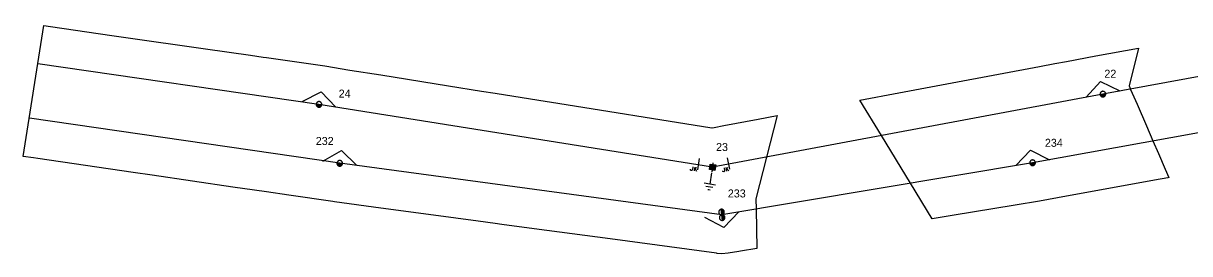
# Model space of a CAD drawing. Extents: x -540879 to -537255, y -1184046 to -1180016.
# Drawn here: x -539690.7 to -539435.6, y -1180909.4 to -1180859 of the extents above; entities that cross this region are included whole.
import ezdxf

# ---------------------------------------------------------------- set-up
doc = ezdxf.new("R2010")
doc.units = 0
for name, color, linetype in [('Vrstva 1', 7, 'Continuous'), ('Vrstva 13', 7, 'Continuous'), ('Vrstva 14', 7, 'Continuous'), ('Vrstva 15', 7, 'Continuous'), ('Vrstva 18', 7, 'Continuous'), ('Vrstva 2', 7, 'Continuous'), ('Vrstva 35', 7, 'Continuous')]:
    doc.layers.add(name, color=color, linetype=linetype)

# ---------------------------------------------------------------- blocks, each defined once
blk = doc.blocks.new('VN840')
at = {"layer": 'Vrstva 15'}
for points in [[(-0.01, 1.41), (-0.01, -1.09)], [(-1.51, -1.24), (-1.51, -1.15)], [(-1.48, -1.35), (-1.51, -1.24)], [(-1.33, -1.42), (-1.48, -1.35)], [(-1.27, -1.42), (-1.33, -1.42)], [(-1.13, -1.35), (-1.27, -1.42)], [(-1.09, -1.24), (-1.13, -1.35)], [(-1.09, -0.59), (-1.09, -1.24)], [(-0.68, -0.59), (-0.68, -1.42)], [(-0.68, -1.11), (-0.27, -0.59)], [(-0.54, -0.94), (-0.2, -1.42)]]:
    blk.add_lwpolyline(points, dxfattribs=at)
blk = doc.blocks.new('VN860')
at = {"layer": 'Vrstva 15'}
for points in [[(-3.74, 0), (0.01, 2.82)], [(0.01, 2.82), (3.76, 0)]]:
    blk.add_lwpolyline(points, dxfattribs=at)
blk = doc.blocks.new('VN440')
at = {"layer": 'Vrstva 2'}
for points in [[(1.22, 0), (1.21, 0.13), (1.19, 0.25), (1.16, 0.38), (1.11, 0.5), (1.05, 0.61), (0.98, 0.72), (0.9, 0.82), (0.81, 0.91), (0.71, 0.99), (0.6, 1.06), (0.49, 1.12), (0.37, 1.16), (0.25, 1.2), (0.12, 1.22), (-0.01, 1.22), (-0.14, 1.22), (-0.26, 1.2), (-0.39, 1.16), (-0.51, 1.12), (-0.62, 1.06), (-0.73, 0.99), (-0.83, 0.91), (-0.92, 0.82), (-1, 0.72), (-1.07, 0.61), (-1.13, 0.5), (-1.18, 0.38), (-1.21, 0.25), (-1.23, 0.13), (-1.24, 0), (-1.23, -0.13), (-1.21, -0.26), (-1.18, -0.38), (-1.13, -0.5), (-1.07, -0.62), (-1, -0.73), (-0.92, -0.83), (-0.83, -0.92), (-0.73, -1), (-0.62, -1.07), (-0.51, -1.13), (-0.39, -1.17), (-0.26, -1.2), (-0.14, -1.23), (-0.01, -1.23), (0.12, -1.23), (0.25, -1.2), (0.37, -1.17), (0.49, -1.13), (0.6, -1.07), (0.71, -1), (0.81, -0.92), (0.9, -0.83), (0.98, -0.73), (1.05, -0.62), (1.11, -0.5), (1.16, -0.38), (1.19, -0.26), (1.21, -0.13), (1.22, 0)], [(-1.24, 0), (1.22, 0)], [(-1.18, -0.34), (1.1, -0.34)], [(-1.01, -0.63), (0.97, -0.63)], [(-0.74, -0.92), (0.68, -0.92)]]:
    blk.add_lwpolyline(points, dxfattribs=at)
blk = doc.blocks.new('VN810')
at = {"layer": 'Vrstva 14'}
for points in [[(0, -1.25), (0, -3.75)], [(1.25, -3.75), (-1.25, -3.75)], [(0.77, -4.37), (-0.8, -4.37)], [(0, -5), (-0.25, -5)], [(0.27, -5), (0, -5)]]:
    blk.add_lwpolyline(points, dxfattribs=at)
blk = doc.blocks.new('VN450')
at = {"layer": 'Vrstva 2'}
for points in [[(0, 0), (-0.01, 0.13), (-0.03, 0.25), (-0.06, 0.38), (-0.11, 0.5), (-0.16, 0.61), (-0.23, 0.72), (-0.31, 0.82), (-0.4, 0.91), (-0.5, 0.99), (-0.61, 1.06), (-0.72, 1.11), (-0.84, 1.16), (-0.97, 1.19), (-1.09, 1.21), (-1.22, 1.22), (-1.35, 1.21), (-1.47, 1.19), (-1.59, 1.16), (-1.71, 1.11), (-1.83, 1.06), (-1.93, 0.99), (-2.03, 0.91), (-2.12, 0.82), (-2.2, 0.72), (-2.27, 0.61), (-2.33, 0.5), (-2.38, 0.38), (-2.41, 0.25), (-2.43, 0.13), (-2.44, 0), (-2.43, -0.13), (-2.41, -0.25), (-2.38, -0.38), (-2.33, -0.5), (-2.27, -0.61), (-2.2, -0.72), (-2.12, -0.82), (-2.03, -0.91), (-1.93, -0.99), (-1.83, -1.06), (-1.71, -1.11), (-1.59, -1.16), (-1.47, -1.19), (-1.35, -1.21), (-1.22, -1.22), (-1.09, -1.21), (-0.97, -1.19), (-0.84, -1.16), (-0.72, -1.11), (-0.61, -1.06), (-0.5, -0.99), (-0.4, -0.91), (-0.31, -0.82), (-0.23, -0.72), (-0.16, -0.61), (-0.11, -0.5), (-0.06, -0.38), (-0.03, -0.25), (-0.01, -0.13), (0, 0)], [(-2.44, 0), (2.44, 0)], [(2.44, 0), (2.43, 0.13), (2.41, 0.25), (2.38, 0.38), (2.33, 0.5), (2.27, 0.61), (2.2, 0.72), (2.12, 0.82), (2.03, 0.91), (1.94, 0.99), (1.83, 1.06), (1.71, 1.11), (1.6, 1.16), (1.47, 1.19), (1.35, 1.21), (1.22, 1.22), (1.09, 1.21), (0.97, 1.19), (0.84, 1.16), (0.72, 1.11), (0.61, 1.06), (0.5, 0.99), (0.4, 0.91), (0.31, 0.82), (0.23, 0.72), (0.16, 0.61), (0.11, 0.5), (0.06, 0.38), (0.03, 0.25), (0.01, 0.13), (0, 0), (0.01, -0.13), (0.03, -0.25), (0.06, -0.38), (0.11, -0.5), (0.16, -0.61), (0.23, -0.72), (0.31, -0.82), (0.4, -0.91), (0.5, -0.99), (0.61, -1.06), (0.72, -1.11), (0.84, -1.16), (0.97, -1.19), (1.09, -1.21), (1.22, -1.22), (1.35, -1.21), (1.47, -1.19), (1.6, -1.16), (1.71, -1.11), (1.83, -1.06), (1.94, -0.99), (2.03, -0.91), (2.12, -0.82), (2.2, -0.72), (2.27, -0.61), (2.33, -0.5), (2.38, -0.38), (2.41, -0.25), (2.43, -0.13), (2.44, 0)], [(-2.4, -0.31), (-0.04, -0.31)], [(-2.26, -0.61), (-0.17, -0.61)], [(-2.01, -0.92), (-0.42, -0.92)], [(0.04, -0.31), (2.4, -0.31)], [(0.17, -0.61), (2.27, -0.61)], [(0.42, -0.92), (2.02, -0.92)]]:
    blk.add_lwpolyline(points, dxfattribs=at)
blk = doc.blocks.new('VN470')
at = {"layer": 'Vrstva 2'}
for points in [[(-1.23, 1.22), (1.23, 1.22)], [(-1.23, -1.23), (-1.23, 1.22)], [(-0.92, 0.9), (0.92, 0.9)], [(-0.92, -0.95), (-0.92, 0.9)], [(-0.61, 0.61), (0.61, 0.61)], [(-0.61, -0.62), (-0.61, 0.61)], [(-0.31, -0.27), (-0.31, 0.34)], [(-0.31, 0.34), (0.31, 0.34)], [(0, 1.22), (0, 1.97)], [(0.31, 0.34), (0.31, -0.27)], [(0.61, 0.61), (0.61, -0.62)], [(0.92, 0.9), (0.92, -0.95)], [(1.23, 1.22), (1.23, -1.23)], [(1.23, -1.23), (-1.23, -1.23)], [(0.92, -0.95), (-0.92, -0.95)], [(0.61, -0.62), (-0.61, -0.62)], [(0.31, -0.27), (-0.31, -0.27)], [(0, -1.23), (0, -1.98)]]:
    blk.add_lwpolyline(points, dxfattribs=at)

msp = doc.modelspace()

# ---------------------------------------------------------------- linework, layer by layer
at = {"layer": 'Vrstva 1'}
for points in [[(-539368.99, -1180859.02), (-539384.94, -1180861.76), (-539454.57, -1180874.5), (-539539.93, -1180890.5), (-539626, -1180876.75), (-539687.49, -1180867.91)], [(-539376.35, -1180872.85), (-539386.09, -1180874.33), (-539469.94, -1180889.51), (-539537.91, -1180900.89), (-539621.46, -1180889.63), (-539689.34, -1180879.74)]]:
    msp.add_lwpolyline(points, dxfattribs=at)
at = {"layer": 'Vrstva 35'}
for points in [[(-539686.17, -1180859.51), (-539684.72, -1180859.72), (-539671.29, -1180861.65), (-539668.73, -1180862.02), (-539650.83, -1180864.59), (-539641, -1180866.01), (-539638.18, -1180866.41), (-539637.5, -1180866.51), (-539624.72, -1180868.35), (-539619.23, -1180869.23), (-539612.5, -1180870.3), (-539597.67, -1180872.67), (-539590.43, -1180873.82), (-539587.5, -1180874.29), (-539576.11, -1180876.11), (-539575.56, -1180876.2), (-539540.09, -1180881.88), (-539540.05, -1180881.87), (-539539.55, -1180881.78), (-539537.5, -1180881.39), (-539529.98, -1180879.98), (-539525.84, -1180879.21), (-539528.16, -1180888.29), (-539530.48, -1180897.39), (-539530.43, -1180899.63), (-539530.26, -1180908.22), (-539533.82, -1180908.82), (-539534.2, -1180908.88), (-539536.5, -1180909.27), (-539536.55, -1180909.27), (-539537.91, -1180909.39), (-539538.92, -1180909.32), (-539539.04, -1180909.3), (-539562.36, -1180906.17), (-539578.94, -1180903.93), (-539586.02, -1180902.98), (-539587.5, -1180902.78), (-539591.16, -1180902.29), (-539600.97, -1180900.97), (-539612.5, -1180899.41), (-539622.64, -1180898.05), (-539623, -1180898), (-539632.59, -1180896.6), (-539637.5, -1180895.88), (-539640.1, -1180895.5), (-539644.82, -1180894.82), (-539662.5, -1180892.24), (-539666.64, -1180891.64), (-539687.5, -1180888.6), (-539688.46, -1180888.46), (-539690.66, -1180888.14)], [(-539448.84, -1180872.69), (-539448.54, -1180873.4), (-539448.5, -1180873.5), (-539447.09, -1180876.73), (-539445.07, -1180881.4), (-539443.62, -1180884.74), (-539442.42, -1180887.5), (-539440.94, -1180890.94), (-539440.15, -1180892.75), (-539440.4, -1180892.8), (-539443.32, -1180893.32), (-539458.09, -1180896), (-539462.5, -1180896.8), (-539468.47, -1180897.88), (-539473.76, -1180898.76), (-539487.5, -1180901.06), (-539491.91, -1180901.8), (-539496.66, -1180893.98), (-539502.99, -1180883.57), (-539507.71, -1180875.81), (-539499.21, -1180874.22), (-539487.5, -1180872.02), (-539468.45, -1180868.45), (-539465.07, -1180867.82), (-539462.5, -1180867.34), (-539456.11, -1180866.14), (-539446.81, -1180864.44)]]:
    msp.add_lwpolyline(points, close=True, dxfattribs=at)

# ---------------------------------------------------------------- block references
at = {"layer": 'Vrstva 13', "xscale": 0.5}
for name, p, yscale, rotation in [('VN440', (-539454.57, -1180874.5), 0.5000000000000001, 10.61368333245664), ('VN440', (-539626, -1180876.75), 0.5, -8.184511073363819), ('VN440', (-539621.46, -1180889.63), 0.5, -8.291100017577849), ('VN440', (-539469.94, -1180889.51), 0.5000000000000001, 9.503538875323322), ('VN470', (-539539.93, -1180890.5), 0.5, -9.257947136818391), ('VN450', (-539537.9, -1180900.89), 0.5, 96.86141941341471)]:
    msp.add_blockref(name, p, dxfattribs=dict(at, yscale=yscale, rotation=rotation))
at = {"layer": 'Vrstva 15', "rotation": -9.257947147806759}
msp.add_blockref('VN810', (-539539.93, -1180890.5), dxfattribs=at)
at = {"layer": 'Vrstva 18'}
for name, p, rotation in [('VN860', (-539454.57, -1180874.5), 10.613030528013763), ('VN860', (-539626, -1180876.75), -9.257836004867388), ('VN860', (-539621.46, -1180889.63), -7.671480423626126), ('VN860', (-539469.94, -1180889.51), 9.505052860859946), ('VN840', (-539543.06, -1180890), -9.07423063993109), ('VN840', (-539536.45, -1180889.84), 10.613738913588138), ('VN860', (-539537.91, -1180900.88), -170.40142507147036)]:
    msp.add_blockref(name, p, dxfattribs=dict(at, rotation=rotation))

# ---------------------------------------------------------------- texts
at = {"layer": 'Vrstva 14'}
for s, p in [('22', (-539454.25, -1180870.92)), ('24', (-539621.69, -1180875.26)), ('232', (-539626.7, -1180885.62)), ('23', (-539539.17, -1180886.94)), ('234', (-539467.25, -1180886.02)), ('233', (-539536.59, -1180897.09))]:
    msp.add_text(s, height=1.75, dxfattribs=at).set_placement(p)

doc.saveas('drawing.dxf')
